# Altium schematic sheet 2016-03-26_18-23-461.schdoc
size 474 x 210 mm; SheetNumber: 1; SheetTotal: 1
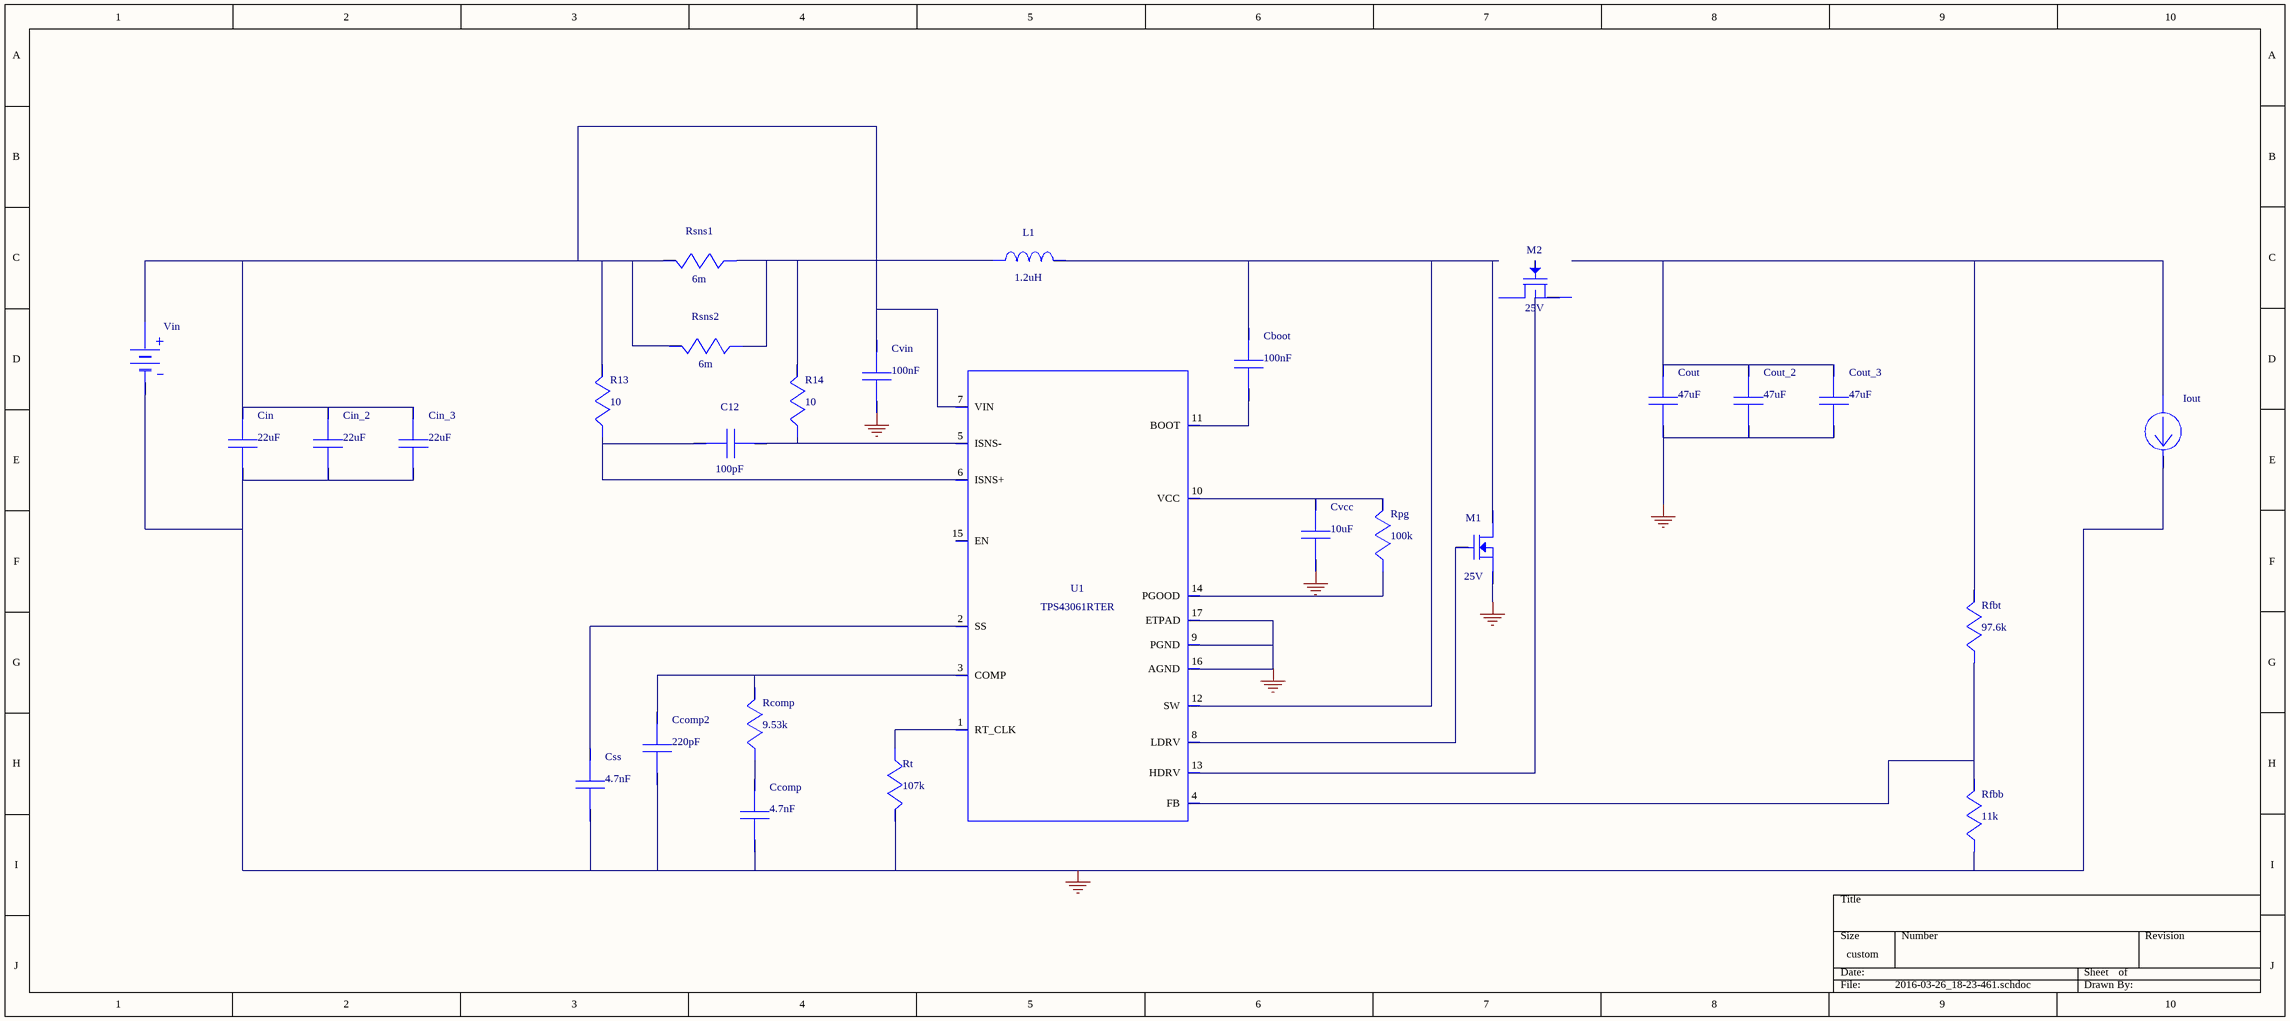
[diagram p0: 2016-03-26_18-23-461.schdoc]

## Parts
C12  value 100pF  (hidden comment: 06035A101JAT2A)
Cboot  value 100nF  (hidden comment: 08053C104KAT2A)
Ccomp  value 4.7nF  (hidden comment: CC0805KRX7R9BB472)
Ccomp2  value 220pF  (hidden comment: CC0805JRNPO9BN221)
Cin  value 22uF  (hidden comment: C3225X6S1C226M)
Cin_2  value 22uF  (hidden comment: C3225X6S1C226M)
Cin_3  value 22uF  (hidden comment: C3225X6S1C226M)
Cout  value 47uF  (hidden comment: C3216X5R1E476M160AC)
Cout_2  value 47uF  (hidden comment: C3216X5R1E476M160AC)
Cout_3  value 47uF  (hidden comment: C3216X5R1E476M160AC)
Css  value 4.7nF  (hidden comment: GRM188R71E472KA01D)
Cvcc  value 10uF  (hidden comment: GRM188R61C106MA73D)
Cvin  value 100nF  (hidden comment: 08053C104KAT2A)
Iout  WB_CURRENT_LOAD  (value not drawn)
L1  value 1.2uH  (hidden comment: MLC1255-122MLB)
M1  value 25V  (hidden comment: CSD16323Q3)
M2  value 25V  (hidden comment: CSD16340Q3)
R13  value 10  (hidden comment: CRCW040210R0FKED)
R14  value 10  (hidden comment: CRCW040210R0FKED)
Rcomp  value 9.53k  (hidden comment: CRCW04029K53FKED)
Rfbb  value 11k  (hidden comment: CRCW040211K0FKED)
Rfbt  value 97.6k  (hidden comment: CRCW040297K6FKED)
Rpg  value 100k  (hidden comment: CRCW0402100KFKED)
Rsns1  value 6m  (hidden comment: PMR100HZPFU6L00)
Rsns2  value 6m  (hidden comment: PMR100HZPFU6L00)
Rt  value 107k  (hidden comment: CRCW0402107KFKED)
U1  TPS43061RTER
Vin  WB_BATTERY  (value not drawn)

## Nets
0: Ccomp.2 Ccomp2.2 Cin.2 Cin_2.2 Cin_3.2 Cout.2 Cout_2.2 Cout_3.2 Css.2 Cvcc.2 Cvin.2 Iout.2(-) M1.1(Source) M1.2(Source) M1.3(Source) Rfbb.2 Rt.1 U1.9(PGND) U1.16(AGND) U1.17(ETPAD) Vin.2(-)
NetC12_1: C12.1 R13.2 U1.6(ISNS+)
NetC12_2: C12.2 R14.2 U1.5(ISNS-)
NetCboot_1: Cboot.1 L1.1 M1.5(Drain) M1.6(Drain) M1.7(Drain) M1.8(Drain) M1.9(Drain) U1.12(SW)
NetCboot_2: Cboot.2 U1.11(BOOT)
NetCcomp2_1: Ccomp2.1 Rcomp.1 U1.3(COMP)
NetCcomp_1: Ccomp.1 Rcomp.2
NetCin_1: Cin.1 Cin_2.1 Cin_3.1 Cvin.1 R13.1 Rsns1.1 Rsns2.1 U1.7(VIN) Vin.1(+)
NetCout_1: Cout.1 Cout_2.1 Cout_3.1 Iout.1(+) Rfbt.1
NetCss_1: Css.1 U1.2(SS)
NetCvcc_1: Cvcc.1 Rpg.1 U1.10(VCC)
NetL1_2: L1.2 R14.1 Rsns1.2 Rsns2.2
NetM1_4: M1.4(Gate) U1.8(LDRV)
NetM2_1: M2.1(Source) M2.2(Source) M2.3(Source)
NetM2_5: M2.5(Drain) M2.6(Drain) M2.7(Drain) M2.8(Drain) M2.9(Drain)
NetRfbb_1: Rfbb.1 Rfbt.2 U1.4(FB)
NetRpg_2: Rpg.2 U1.14(PGOOD)
NetRt_2: Rt.2 U1.1(RT_CLK)

Not connected (* = marked no-connect by the designer): M2 4(Gate); U1 13(HDRV) 15(EN)

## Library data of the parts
C12 = 06035A101JAT2A: Manufacturer Name: AVX
Cboot Cvin = 08053C104KAT2A: Manufacturer Name: AVX
Ccomp = CC0805KRX7R9BB472: CC0805KRX7R9BB47; Manufacturer Name: Yageo America
Ccomp2 = CC0805JRNPO9BN221: CC0805JRNPO9BN22; Manufacturer Name: Yageo America
Cin Cin_2 Cin_3 = C3225X6S1C226M: Manufacturer Name: TDK
Cout Cout_2 Cout_3 = C3216X5R1E476M160AC: C3216X5R1E476M16; Manufacturer Name: TDK
Css = GRM188R71E472KA01D: GRM188R71E472KA0; Manufacturer Name: MuRata
Cvcc = GRM188R61C106MA73D: GRM188R61C106MA7; Manufacturer Name: MuRata
Iout = WB_CURRENT_LOAD: Value: UNLISTED
L1 = MLC1255-122MLB: Manufacturer Name: Coilcraft
M1 = CSD16323Q3: Manufacturer Name: Texas Instruments
M2 = CSD16340Q3: Manufacturer Name: Texas Instruments
R13 R14 = CRCW040210R0FKED: Manufacturer Name: Vishay-Dale
Rcomp = CRCW04029K53FKED: Manufacturer Name: Vishay-Dale
Rfbb = CRCW040211K0FKED: Manufacturer Name: Vishay-Dale
Rfbt = CRCW040297K6FKED: Manufacturer Name: Vishay-Dale
Rpg = CRCW0402100KFKED: Manufacturer Name: Vishay-Dale
Rsns1 Rsns2 = PMR100HZPFU6L00: Manufacturer Name: Rohm
Rt = CRCW0402107KFKED: Manufacturer Name: Vishay-Dale
U1 = TPS43061RTER: Manufacturer Name: Texas Instruments
Vin = WB_BATTERY: Value: UNLISTED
